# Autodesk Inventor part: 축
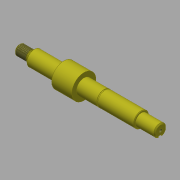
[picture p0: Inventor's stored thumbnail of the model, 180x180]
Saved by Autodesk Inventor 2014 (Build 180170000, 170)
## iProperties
Created: 2016-08
Part Number: 축
Material: 강철, 탄소
Document SubType Name: Modeling
Designer: mduedu
Density: 7.87 g/cm^3
Appearance: Canary
Author: mduedu
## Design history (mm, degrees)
sketch "스케치1"
  geometry: L1 (-70, 0)-(70, 0); L2 (-70, 0)-(-70, 5); L3 (-70, 5)-(-56, 5); L4 (-56, 5)-(-56, 7.5); L5 (-56, 7.5)-(51, 7.5); L6 (51, 7.5)-(51, 6); L7 (51, 6)-(70, 6); L8 (70, 6)-(70, 0); 2 further points
  constraints: 16 end point, 5 parallel, 2 perpendicular, 1 coincident, 1 horizontal, 1 midpoint
  dimensions: "d0" = 140 distance of L1.start L1.end; "d2" = 14 distance of L2.end L3.end; "d3" = 19 distance of L6.end L7.end; "d4" = 10 diameter of L3 L1; "d5" = 15 diameter of L5 L1; "d6" = 12 diameter of L7 L1
revolve "회전1" sketch "스케치1" stored, may be unused: angle "d7" = 90 deg
sketch "스케치2"
  geometry: L1 (-56, -5)-(-56, 5) reference; L2 (70, -6)-(70, 6) reference; L3 (-56, 0)-(70, 0); L4 (-58, 4.5)-(-58, 5); L5 (-58, 5)-(-56, 5); L6 (-56, 5)-(-56, 4.5); L7 (-58, 4.5)-(-56, 4.5); 1 further point
  constraints: 10 end point, 2 midpoint, 1 parallel, 1 perpendicular, 1 point on line
  dimensions: "d8" = 2 distance of L4.end L5.end; "d10" = 10 diameter of L5 L3; "d11" = 9 diameter of L7 L3
revolve "회전2" sketch "스케치2" stored, may be unused: angle "d12" = 90 deg
node "작업 평면1"
sketch "스케치3"
  geometry: C1 r 12 at (0, 0); 1 further point
  constraints: 1 centre point, 1 coincident
  dimensions: "d15" = 24 diameter of C1
extrude "돌출1" join sketch "스케치3" distance "d16" = 20; taper "d17" = 0 deg
sketch "스케치5"
  geometry: L1 (-70, -5)-(-70, 5) reference; L2 (70, -6)-(70, 6) reference; L3 (-70, 0)-(70, 0); L4 (-6, 7.5)-(51, 7.5) reference; L5 (15.15, 7.5)-(14, 7.5); L6 (14, 7.5)-(14, 7.15); L7 (14, 7.15)-(15.15, 7.15); L8 (15.15, 7.15)-(15.15, 7.5); 1 further point
  constraints: 10 end point, 2 midpoint, 2 parallel, 1 horizontal, 1 perpendicular, 1 point on line
  dimensions: "d19" = 56 distance between parallel lines of L6 L2; "d20" = 1.15 distance between parallel lines of L8 L6; "d21" = 14.3 diameter of L7 L3
revolve "회전3" sketch "스케치5" stored, may be unused: angle "d22" = 90 deg
node "작업 평면3"
sketch "스케치6"
  geometry: L1 (9.5, 7.5)-(9.5, -7.5) reference; L2 (7.5, 2)-(-9.5, 2); L3 (-9.5, 2)-(-9.5, -2); L4 (-9.5, -2)-(7.5, -2); L5 (-9.5, 6)-(-9.5, -6) reference; A1 r 2 centre (7.5, 0) between (7.5, -2) and (7.5, 2); 2 further points
  constraints: 6 end point, 3 tangent, 2 midpoint, 2 point on circle, 1 centre point, 1 horizontal, 1 horizontal alignment, 1 parallel, 1 perpendicular
  dimensions: "d23" = 4 distance between parallel lines of L4 L2
extrude "돌출2" cut sketch "스케치6" distance "d25" = 2.5; taper "d26" = 0 deg
feature "스레드1" dims "d27" = 10, "d28" = 0
chamfer "모따기5" distance "d41" = 0.5; stored, may be unused: second distance "d42" = 2, angle "d43" = 45 deg
chamfer "모따기6" distance "d44" = 0.5; stored, may be unused: second distance "d45" = 2, angle "d46" = 45 deg
chamfer "모따기7" distance "d47" = 1; stored, may be unused: second distance "d48" = 2, angle "d49" = 45 deg
chamfer "모따기8" distance "d50" = 1; stored, may be unused: second distance "d51" = 2, angle "d52" = 45 deg
sketch "스케치8"
  geometry: 1 further point
hole "구멍1" sketch "스케치8" at (2, 3.5) diameter "d53" = 3.242; stored, may be unused: countersink angle "d57" = 90 deg, drill point angle "d59" = 120 deg; dims "d54" = 10, "d55" = 4, "d56" = 2, "d58" = 12
node "솔리드1"
other parameters: "d13" = -44
